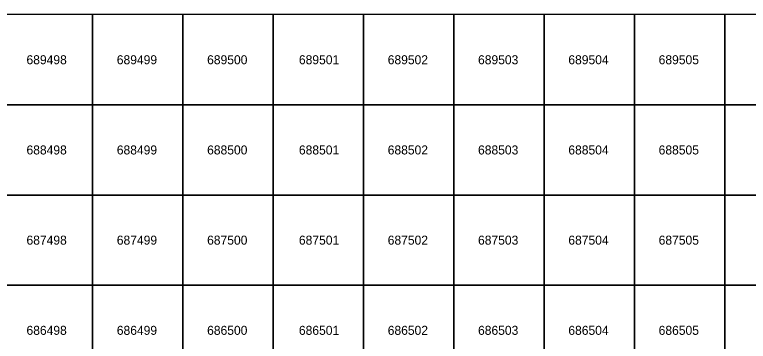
# Model space of a CAD drawing. Extents: x 25485000 to 25520000, y 6656775 to 6690000.
# Drawn here: x 25498138 to 25506262, y 6686378 to 6690000 of the extents above; entities that cross this region are included whole.
import ezdxf

# ---------------------------------------------------------------- set-up
doc = ezdxf.new("R2010")
doc.units = 0
doc.layers.add('Level 63', color=7, linetype='Continuous')

msp = doc.modelspace()

# ---------------------------------------------------------------- linework, layer by layer
at = {"layer": 'Level 63'}
for points in [[(25498000, 6689000), (25499000, 6689000), (25499000, 6690000), (25498000, 6690000)], [(25499000, 6689000), (25500000, 6689000), (25500000, 6690000), (25499000, 6690000)], [(25500000, 6689000), (25501000, 6689000), (25501000, 6690000), (25500000, 6690000)], [(25501000, 6689000), (25502000, 6689000), (25502000, 6690000), (25501000, 6690000)], [(25502000, 6689000), (25503000, 6689000), (25503000, 6690000), (25502000, 6690000)], [(25503000, 6689000), (25504000, 6689000), (25504000, 6690000), (25503000, 6690000)], [(25504000, 6689000), (25505000, 6689000), (25505000, 6690000), (25504000, 6690000)], [(25505000, 6689000), (25506000, 6689000), (25506000, 6690000), (25505000, 6690000)], [(25506000, 6689000), (25507000, 6689000), (25507000, 6690000), (25506000, 6690000)], [(25498000, 6688000), (25499000, 6688000), (25499000, 6689000), (25498000, 6689000)], [(25499000, 6688000), (25500000, 6688000), (25500000, 6689000), (25499000, 6689000)], [(25500000, 6688000), (25501000, 6688000), (25501000, 6689000), (25500000, 6689000)], [(25501000, 6688000), (25502000, 6688000), (25502000, 6689000), (25501000, 6689000)], [(25502000, 6688000), (25503000, 6688000), (25503000, 6689000), (25502000, 6689000)], [(25503000, 6688000), (25504000, 6688000), (25504000, 6689000), (25503000, 6689000)], [(25504000, 6688000), (25505000, 6688000), (25505000, 6689000), (25504000, 6689000)], [(25505000, 6688000), (25506000, 6688000), (25506000, 6689000), (25505000, 6689000)], [(25506000, 6688000), (25507000, 6688000), (25507000, 6689000), (25506000, 6689000)], [(25498000, 6687000), (25499000, 6687000), (25499000, 6688000), (25498000, 6688000)], [(25499000, 6687000), (25500000, 6687000), (25500000, 6688000), (25499000, 6688000)], [(25500000, 6687000), (25501000, 6687000), (25501000, 6688000), (25500000, 6688000)], [(25501000, 6687000), (25502000, 6687000), (25502000, 6688000), (25501000, 6688000)], [(25502000, 6687000), (25503000, 6687000), (25503000, 6688000), (25502000, 6688000)], [(25503000, 6687000), (25504000, 6687000), (25504000, 6688000), (25503000, 6688000)], [(25504000, 6687000), (25505000, 6687000), (25505000, 6688000), (25504000, 6688000)], [(25505000, 6687000), (25506000, 6687000), (25506000, 6688000), (25505000, 6688000)], [(25506000, 6687000), (25507000, 6687000), (25507000, 6688000), (25506000, 6688000)], [(25498000, 6686000), (25499000, 6686000), (25499000, 6687000), (25498000, 6687000)], [(25499000, 6686000), (25500000, 6686000), (25500000, 6687000), (25499000, 6687000)], [(25500000, 6686000), (25501000, 6686000), (25501000, 6687000), (25500000, 6687000)], [(25501000, 6686000), (25502000, 6686000), (25502000, 6687000), (25501000, 6687000)], [(25502000, 6686000), (25503000, 6686000), (25503000, 6687000), (25502000, 6687000)], [(25503000, 6686000), (25504000, 6686000), (25504000, 6687000), (25503000, 6687000)], [(25504000, 6686000), (25505000, 6686000), (25505000, 6687000), (25504000, 6687000)], [(25505000, 6686000), (25506000, 6686000), (25506000, 6687000), (25505000, 6687000)], [(25506000, 6686000), (25507000, 6686000), (25507000, 6687000), (25506000, 6687000)]]:
    msp.add_lwpolyline(points, close=True, dxfattribs=at)

# ---------------------------------------------------------------- texts
for s, p in [('689498', (25498268.5, 6689450)), ('689499', (25499268.5, 6689450)), ('689500', (25500268.5, 6689450)), ('689501', (25501285.1, 6689450)), ('689502', (25502268.5, 6689450)), ('689503', (25503268.5, 6689450)), ('689504', (25504268.5, 6689450)), ('689505', (25505268.5, 6689450)), ('688498', (25498268.5, 6688450)), ('688499', (25499268.5, 6688450)), ('688500', (25500268.5, 6688450)), ('688501', (25501285.1, 6688450)), ('688502', (25502268.5, 6688450)), ('688503', (25503268.5, 6688450)), ('688504', (25504268.5, 6688450)), ('688505', (25505268.5, 6688450)), ('687498', (25498268.5, 6687450)), ('687499', (25499268.5, 6687450)), ('687500', (25500268.5, 6687450)), ('687501', (25501285.1, 6687450)), ('687502', (25502268.5, 6687450)), ('687503', (25503268.5, 6687450)), ('687504', (25504268.5, 6687450)), ('687505', (25505268.5, 6687450)), ('686498', (25498268.5, 6686450)), ('686499', (25499268.5, 6686450)), ('686500', (25500268.5, 6686450)), ('686501', (25501285.1, 6686450)), ('686502', (25502268.5, 6686450)), ('686503', (25503268.5, 6686450)), ('686504', (25504268.5, 6686450)), ('686505', (25505268.5, 6686450))]:
    msp.add_text(s, height=100, dxfattribs=at).set_placement(p)

doc.saveas('drawing.dxf')
